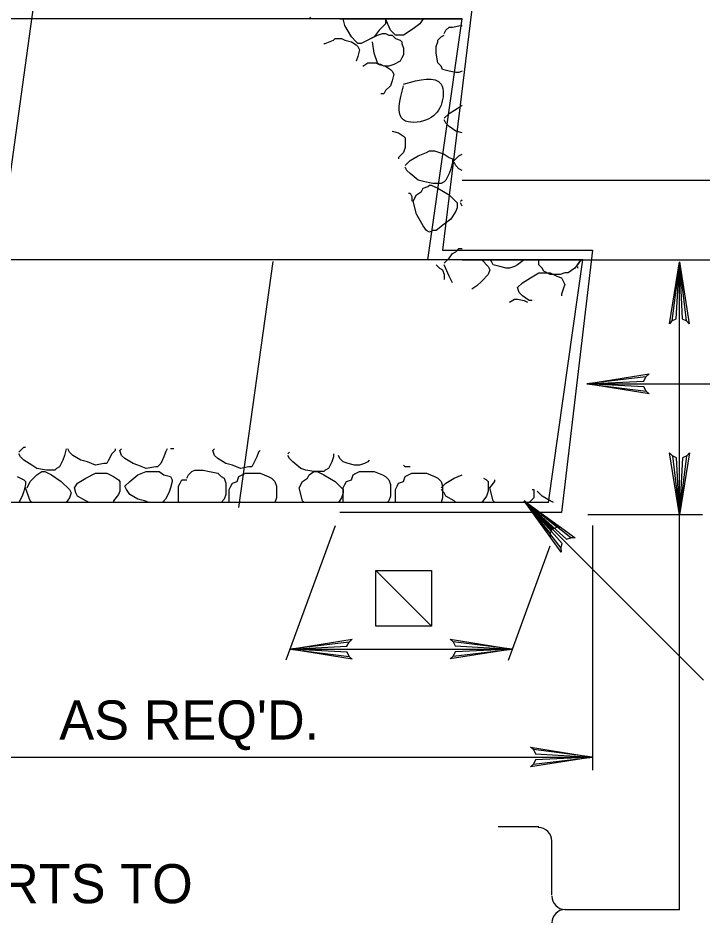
# Model space of a CAD drawing. Extents: x 593 to 1473, y 721 to 1315.
# Drawn here: x 928.2 to 980.7, y 1112.6 to 1182.1 of the extents above; entities that cross this region are included whole.
import ezdxf

# ---------------------------------------------------------------- set-up
doc = ezdxf.new("R2010")
doc.units = 0
doc.layers.add('1', color=7, linetype='Continuous')
doc.layers.add('2', color=7, linetype='Continuous')

msp = doc.modelspace()

# ---------------------------------------------------------------- linework, layer by layer
at = {"layer": '1'}
msp.add_line((959.933, 1135.405), (955.656, 1139.679), dxfattribs=at)
for points in [[(978.373, 1158.838), (978.701, 1159.007), (978.942, 1163.379), (978.373, 1158.838), (978.173, 1158.605), (978.942, 1163.379), (979.159, 1159.011), (979.484, 1158.851), (978.942, 1163.379), (979.701, 1158.605), (979.484, 1158.851)], [(978.373, 1158.838), (978.701, 1159.007), (978.942, 1163.379), (978.373, 1158.838), (978.173, 1158.605), (978.942, 1163.379), (979.159, 1159.011), (979.484, 1158.851), (978.942, 1163.379), (979.701, 1158.605), (979.484, 1158.851)], [(976.382, 1153.439), (976.213, 1153.768), (971.841, 1154.009), (976.382, 1153.439), (976.615, 1153.24), (971.841, 1154.009), (976.209, 1154.225), (976.369, 1154.55), (971.841, 1154.009), (976.615, 1154.768), (976.369, 1154.55)], [(979.513, 1148.491), (979.184, 1148.322), (978.942, 1143.95), (979.513, 1148.491), (979.712, 1148.724), (978.942, 1143.95), (978.726, 1148.318), (978.401, 1148.478), (978.942, 1143.95), (978.184, 1148.724), (978.401, 1148.478)], [(969.841, 1141.407), (969.954, 1141.759), (967.033, 1145.021), (969.841, 1141.407), (969.865, 1141.102), (967.033, 1145.021), (970.275, 1142.085), (970.617, 1142.202), (967.033, 1145.021), (970.945, 1142.182), (970.617, 1142.202)], [(953.617, 1133.08), (953.448, 1133.409), (949.076, 1133.65), (953.617, 1133.08), (953.85, 1132.881), (949.076, 1133.65), (953.444, 1133.866), (953.604, 1134.191), (949.076, 1133.65), (953.85, 1134.409), (953.604, 1134.191)], [(961.58, 1134.22), (961.749, 1133.891), (966.121, 1133.65), (961.58, 1134.22), (961.347, 1134.419), (966.121, 1133.65), (961.753, 1133.434), (961.593, 1133.109), (966.121, 1133.65), (961.347, 1132.891), (961.593, 1133.109)], [(961.58, 1134.22), (961.749, 1133.891), (966.121, 1133.65), (961.58, 1134.22), (961.347, 1134.419), (966.121, 1133.65), (961.753, 1133.434), (961.593, 1133.109), (966.121, 1133.65), (961.347, 1132.891), (961.593, 1133.109)], [(967.743, 1125.933), (967.912, 1125.605), (972.283, 1125.363), (967.743, 1125.933), (967.51, 1126.133), (972.283, 1125.363), (967.915, 1125.147), (967.756, 1124.822), (972.283, 1125.363), (967.51, 1124.605), (967.756, 1124.822)]]:
    msp.add_lwpolyline(points, dxfattribs=at)
for points in [[(959.933, 1135.405), (955.656, 1135.405), (955.656, 1139.679), (959.933, 1139.679)], [(959.933, 1135.405), (955.656, 1139.679), (959.933, 1139.679)]]:
    msp.add_lwpolyline(points, close=True, dxfattribs=at)
at = {"layer": '2'}
for p, q in [((924.158, 1145.021), (934.408, 1219.146)), ((963.033, 1182.771), (960.783, 1164.271)), ((962.283, 1182.021), (910.658, 1182.021)), ((952.908, 1182.021), (962.283, 1182.021)), ((959.658, 1163.521), (962.283, 1182.021)), ((962.283, 1169.646), (997.408, 1169.646)), ((960.783, 1164.271), (972.283, 1164.271)), ((972.283, 1164.271), (969.908, 1144.146)), ((971.533, 1163.521), (908.104, 1163.521)), ((945.158, 1144.521), (947.783, 1163.396)), ((962.283, 1163.521), (971.533, 1163.521)), ((968.908, 1144.896), (971.533, 1163.521)), ((971.533, 1163.521), (997.408, 1163.521)), ((978.942, 1143.95), (978.942, 1163.379)), ((971.841, 1154.009), (1024.591, 1154.009)), ((968.908, 1144.896), (905.658, 1144.896)), ((967.033, 1145.021), (980.783, 1131.271)), ((969.908, 1144.146), (952.908, 1144.146)), ((980.701, 1143.95), (971.924, 1143.95)), ((978.942, 1113.625), (978.942, 1143.95)), ((952.529, 1143.107), (948.765, 1132.798)), ((972.283, 1143.146), (972.283, 1124.363)), ((969.001, 1141.54), (965.803, 1132.78)), ((949.076, 1133.65), (966.121, 1133.65)), ((915.783, 1125.363), (972.283, 1125.363)), ((968.161, 1120), (965.036, 1120)), ((969.161, 1114.75), (969.161, 1118.875)), ((978.942, 1113.625), (970.161, 1113.625))]:
    msp.add_line(p, q, dxfattribs=at)
for points in [[(950.658, 1182.146), (950.533, 1182.021)], [(953.283, 1181.521), (953.158, 1182.021)], [(953.783, 1180.646), (953.283, 1181.521)], [(956.408, 1181.646), (955.908, 1181.146)], [(956.408, 1182.021), (956.408, 1182.021)], [(956.408, 1182.021), (956.408, 1181.646)], [(956.783, 1181.146), (956.408, 1182.021)], [(959.033, 1181.646), (958.533, 1181.271)], [(959.283, 1182.021), (959.033, 1181.646)], [(961.033, 1181.146), (961.283, 1181.396)], [(961.283, 1181.396), (961.533, 1181.396)], [(961.533, 1181.396), (962.158, 1181.521)], [(962.158, 1181.521), (962.283, 1181.521)], [(955.908, 1181.146), (955.533, 1180.646)], [(955.533, 1180.646), (955.783, 1180.771)], [(955.783, 1180.771), (956.158, 1180.896)], [(956.158, 1180.896), (956.408, 1180.896)], [(956.408, 1180.896), (956.658, 1180.771)], [(956.658, 1180.771), (956.908, 1180.771)], [(957.158, 1180.771), (956.783, 1181.146)], [(956.908, 1180.771), (957.158, 1180.521)], [(957.283, 1180.771), (957.158, 1180.771)], [(957.533, 1180.771), (957.283, 1180.771)], [(957.783, 1180.771), (957.533, 1180.771)], [(958.533, 1181.271), (957.783, 1180.771)], [(960.658, 1180.646), (960.908, 1180.771)], [(960.908, 1180.896), (961.033, 1181.146)], [(951.658, 1180.146), (951.783, 1180.146)], [(951.783, 1180.146), (952.408, 1180.396)], [(952.408, 1180.396), (952.533, 1180.521)], [(952.533, 1180.521), (953.033, 1180.521)], [(953.033, 1180.521), (953.283, 1180.396)], [(953.283, 1180.396), (953.783, 1180.271)], [(954.158, 1180.271), (953.783, 1180.646)], [(953.783, 1180.271), (954.158, 1180.021)], [(954.283, 1180.146), (954.158, 1180.271)], [(954.158, 1180.021), (954.283, 1179.896)], [(954.533, 1180.146), (954.283, 1180.146)], [(954.783, 1180.271), (954.533, 1180.146)], [(955.533, 1180.646), (954.783, 1180.271)], [(955.283, 1180.521), (955.533, 1180.646)], [(955.533, 1179.396), (955.408, 1180.271)], [(957.158, 1180.521), (957.533, 1180.396)], [(957.533, 1180.396), (957.658, 1180.271)], [(957.658, 1180.271), (957.658, 1180.146)], [(957.658, 1180.146), (957.783, 1179.771)], [(960.283, 1179.896), (960.408, 1180.271)], [(960.408, 1180.396), (960.658, 1180.646)], [(960.408, 1180.271), (960.408, 1180.396)], [(954.283, 1179.896), (954.408, 1179.646)], [(954.408, 1179.646), (954.283, 1179.146)], [(955.783, 1178.646), (955.533, 1179.396)], [(957.783, 1179.271), (957.658, 1179.021)], [(957.783, 1179.771), (957.783, 1179.521)], [(957.783, 1179.521), (957.783, 1179.271)], [(960.283, 1179.396), (960.283, 1179.896)], [(960.408, 1178.646), (960.283, 1179.396)], [(954.283, 1179.146), (954.158, 1178.771)], [(954.158, 1178.771), (954.158, 1178.771)], [(954.658, 1178.396), (955.033, 1178.646)], [(955.033, 1178.646), (955.158, 1178.646)], [(955.158, 1178.646), (955.658, 1178.646)], [(955.658, 1178.646), (955.908, 1178.521)], [(955.908, 1178.521), (955.783, 1178.646)], [(957.533, 1178.771), (957.033, 1178.521)], [(957.658, 1179.021), (957.533, 1178.771)], [(960.658, 1178.396), (960.408, 1178.646)], [(956.033, 1178.521), (955.908, 1178.521)], [(955.908, 1178.521), (956.408, 1178.396)], [(956.283, 1178.396), (956.033, 1178.521)], [(956.408, 1178.396), (956.283, 1178.396)], [(956.658, 1178.396), (956.408, 1178.396)], [(956.408, 1178.396), (956.783, 1178.146)], [(957.033, 1178.521), (956.658, 1178.396)], [(956.783, 1178.146), (956.908, 1178.021)], [(956.908, 1178.021), (957.033, 1177.771)], [(960.783, 1178.146), (960.658, 1178.396)], [(961.283, 1178.021), (960.783, 1178.146)], [(961.783, 1177.896), (961.283, 1178.021)], [(962.033, 1177.896), (961.783, 1177.896)], [(962.283, 1178.021), (962.033, 1177.896)], [(956.908, 1177.271), (956.783, 1176.896)], [(957.033, 1177.771), (956.908, 1177.271)], [(956.408, 1176.521), (956.283, 1176.271)], [(956.783, 1176.896), (956.408, 1176.521)], [(956.158, 1176.271), (956.033, 1176.271)], [(956.283, 1176.271), (956.158, 1176.271)], [(961.283, 1174.771), (961.908, 1175.146)], [(961.908, 1175.146), (962.283, 1175.396)], [(960.908, 1174.396), (961.283, 1174.771)], [(961.033, 1174.021), (960.908, 1174.271)], [(961.283, 1173.771), (961.033, 1174.021)], [(961.783, 1173.396), (961.283, 1173.771)], [(956.908, 1173.396), (956.908, 1173.396)], [(956.908, 1173.396), (957.408, 1173.271)], [(957.408, 1173.271), (957.783, 1173.021)], [(957.783, 1173.021), (957.908, 1172.896)], [(962.283, 1173.271), (961.783, 1173.396)], [(957.908, 1172.896), (957.908, 1172.646)], [(957.908, 1172.646), (957.908, 1172.146)], [(957.783, 1171.771), (957.408, 1171.396)], [(957.908, 1172.146), (957.783, 1171.771)], [(958.908, 1171.521), (959.533, 1171.771)], [(959.533, 1171.771), (959.783, 1171.896)], [(959.783, 1171.896), (960.158, 1171.896)], [(960.158, 1171.896), (960.533, 1171.771)], [(960.533, 1171.771), (960.908, 1171.646)], [(960.908, 1171.646), (961.283, 1171.396)], [(962.033, 1171.521), (962.283, 1171.646)], [(957.408, 1171.396), (957.408, 1171.271)], [(957.908, 1170.771), (958.283, 1171.146)], [(958.283, 1171.146), (958.908, 1171.521)], [(961.283, 1171.396), (961.533, 1171.271)], [(961.533, 1171.021), (961.408, 1170.521)], [(961.533, 1171.271), (961.533, 1171.021)], [(961.658, 1171.146), (962.033, 1171.521)], [(961.783, 1170.771), (961.658, 1171.021)], [(958.033, 1170.396), (957.908, 1170.646)], [(958.283, 1170.146), (958.033, 1170.396)], [(961.408, 1170.521), (961.283, 1170.146)], [(962.033, 1170.521), (961.783, 1170.771)], [(962.283, 1170.396), (962.033, 1170.521)], [(958.908, 1169.646), (958.283, 1170.146)], [(959.408, 1169.521), (958.908, 1169.646)], [(961.033, 1169.646), (960.908, 1169.521)], [(961.283, 1170.146), (961.033, 1169.646)], [(959.158, 1168.771), (959.283, 1169.021)], [(959.283, 1169.021), (959.658, 1169.146)], [(960.033, 1169.396), (959.408, 1169.521)], [(959.658, 1169.146), (959.783, 1169.271)], [(959.783, 1169.271), (959.908, 1169.271)], [(959.908, 1169.271), (960.408, 1169.021)], [(960.658, 1169.396), (960.033, 1169.396)], [(960.408, 1169.021), (961.283, 1168.521)], [(960.908, 1169.521), (960.658, 1169.396)], [(958.158, 1168.646), (958.283, 1168.646)], [(958.283, 1168.646), (958.408, 1168.396)], [(958.408, 1168.396), (958.408, 1168.271)], [(958.408, 1168.271), (958.408, 1168.021)], [(958.533, 1168.021), (958.783, 1168.521)], [(958.783, 1168.521), (959.158, 1168.771)], [(961.283, 1168.521), (961.908, 1167.896)], [(958.783, 1167.021), (958.533, 1168.021)], [(961.908, 1167.521), (961.783, 1167.271)], [(961.908, 1167.896), (961.908, 1167.521)], [(962.158, 1168.021), (962.283, 1168.146)], [(962.283, 1167.646), (962.158, 1167.896)], [(959.283, 1166.146), (958.783, 1167.021)], [(961.783, 1167.271), (961.408, 1166.646)], [(959.533, 1165.771), (959.283, 1166.146)], [(960.908, 1166.271), (960.283, 1165.771)], [(961.408, 1166.646), (960.908, 1166.271)], [(959.783, 1165.646), (959.533, 1165.771)], [(960.033, 1165.771), (959.783, 1165.646)], [(960.283, 1165.771), (960.033, 1165.771)], [(961.283, 1163.646), (961.533, 1164.021)], [(961.533, 1164.021), (961.783, 1164.146)], [(961.783, 1164.146), (962.033, 1164.396)], [(962.033, 1164.396), (962.158, 1164.396)], [(962.158, 1164.396), (962.283, 1164.396)], [(960.908, 1163.271), (961.283, 1163.646)], [(963.783, 1163.521), (964.283, 1163.021)], [(964.533, 1163.396), (964.408, 1163.521)], [(964.658, 1163.146), (964.533, 1163.396)], [(967.033, 1163.521), (966.533, 1163.146)], [(968.158, 1163.146), (968.158, 1163.521)], [(971.283, 1163.396), (970.908, 1162.896)], [(971.158, 1163.146), (971.408, 1163.521)], [(971.408, 1163.521), (971.283, 1163.396)], [(960.283, 1163.146), (960.283, 1163.146)], [(960.283, 1163.146), (960.533, 1162.896)], [(960.533, 1162.896), (960.783, 1162.771)], [(960.783, 1162.771), (960.908, 1162.396)], [(961.283, 1162.271), (960.908, 1163.146)], [(964.283, 1163.021), (964.408, 1162.771)], [(964.408, 1162.771), (964.283, 1162.396)], [(965.158, 1163.021), (964.658, 1163.146)], [(965.658, 1162.896), (965.158, 1163.021)], [(965.908, 1162.896), (965.658, 1162.896)], [(966.283, 1163.021), (965.908, 1162.896)], [(966.533, 1163.146), (966.283, 1163.021)], [(968.408, 1162.896), (968.158, 1163.146)], [(968.533, 1162.646), (968.408, 1162.896)], [(969.033, 1162.396), (968.533, 1162.646)], [(970.908, 1162.896), (970.408, 1162.521)], [(971.158, 1162.896), (971.158, 1163.021)], [(960.908, 1162.396), (960.908, 1162.021)], [(960.908, 1162.021), (960.908, 1162.021)], [(961.533, 1161.771), (961.283, 1162.271)], [(964.283, 1162.396), (963.783, 1161.896)], [(966.908, 1161.771), (967.533, 1162.146)], [(967.533, 1162.146), (968.158, 1162.521)], [(968.158, 1162.521), (968.283, 1162.521)], [(968.283, 1162.521), (968.783, 1162.521)], [(968.783, 1162.521), (969.033, 1162.521)], [(969.033, 1162.521), (969.533, 1162.271)], [(969.408, 1162.396), (969.033, 1162.396)], [(969.783, 1162.396), (969.408, 1162.396)], [(969.533, 1162.271), (969.908, 1162.146)], [(970.158, 1162.521), (969.783, 1162.396)], [(969.908, 1162.146), (970.033, 1161.896)], [(970.408, 1162.521), (970.158, 1162.521)], [(963.408, 1161.521), (963.033, 1161.271)], [(963.783, 1161.896), (963.408, 1161.521)], [(966.533, 1161.396), (966.908, 1161.771)], [(966.658, 1161.021), (966.533, 1161.396)], [(970.033, 1161.271), (969.908, 1160.896)], [(970.033, 1161.896), (970.158, 1161.646)], [(970.158, 1161.646), (970.033, 1161.271)], [(965.908, 1160.271), (966.283, 1160.521)], [(966.283, 1160.521), (966.408, 1160.521)], [(966.408, 1160.521), (966.533, 1160.521)], [(966.533, 1160.521), (967.033, 1160.396)], [(966.908, 1160.771), (966.658, 1161.021)], [(967.408, 1160.396), (966.908, 1160.771)], [(969.908, 1160.896), (969.908, 1160.771)], [(965.908, 1160.271), (965.908, 1160.271)], [(967.033, 1160.396), (967.283, 1160.271)], [(967.658, 1160.396), (967.408, 1160.396)], [(928.283, 1148.771), (928.658, 1149.146)], [(928.658, 1149.146), (928.783, 1149.146)], [(931.908, 1149.021), (931.783, 1148.521)], [(931.908, 1149.021), (931.908, 1149.021)], [(932.158, 1148.771), (932.033, 1149.021)], [(932.408, 1148.521), (932.158, 1148.771)], [(935.658, 1148.896), (935.408, 1148.646)], [(935.658, 1149.021), (935.658, 1148.896)], [(936.033, 1148.896), (936.158, 1149.021)], [(936.158, 1148.521), (936.033, 1148.896)], [(939.533, 1148.771), (939.408, 1148.396)], [(939.658, 1149.021), (939.533, 1148.771)], [(940.158, 1149.021), (939.908, 1149.021)], [(939.908, 1149.021), (939.908, 1149.021)], [(940.158, 1149.021), (940.158, 1149.021)], [(943.158, 1148.896), (943.283, 1149.021)], [(943.283, 1148.521), (943.158, 1148.896)], [(946.658, 1148.771), (946.533, 1148.396)], [(946.783, 1148.896), (946.658, 1148.771)], [(948.908, 1148.646), (949.033, 1148.771)], [(928.408, 1148.396), (928.283, 1148.646)], [(928.658, 1148.146), (928.408, 1148.396)], [(929.283, 1147.771), (928.658, 1148.146)], [(931.658, 1148.146), (931.408, 1147.646)], [(931.783, 1148.521), (931.658, 1148.146)], [(933.033, 1148.146), (932.408, 1148.521)], [(933.533, 1148.021), (933.033, 1148.146)], [(934.158, 1147.771), (933.533, 1148.021)], [(935.158, 1148.146), (935.033, 1147.896)], [(935.408, 1148.646), (935.158, 1148.146)], [(936.408, 1148.271), (936.158, 1148.521)], [(937.033, 1147.896), (936.408, 1148.271)], [(939.408, 1148.396), (939.158, 1147.896)], [(943.533, 1148.271), (943.283, 1148.521)], [(944.158, 1147.896), (943.533, 1148.271)], [(946.533, 1148.396), (946.283, 1147.896)], [(949.033, 1148.271), (948.908, 1148.521)], [(949.283, 1148.021), (949.033, 1148.271)], [(949.908, 1147.521), (949.283, 1148.021)], [(952.283, 1148.021), (952.033, 1147.521)], [(952.408, 1148.396), (952.283, 1148.021)], [(952.408, 1148.646), (952.408, 1148.396)], [(952.908, 1148.271), (952.783, 1148.521)], [(953.158, 1148.021), (952.908, 1148.271)], [(953.533, 1147.896), (953.158, 1148.021)], [(955.033, 1148.021), (954.783, 1147.896)], [(955.158, 1148.146), (955.033, 1148.021)], [(929.658, 1147.521), (929.283, 1147.771)], [(930.408, 1147.396), (929.658, 1147.521)], [(931.033, 1147.396), (930.408, 1147.396)], [(931.158, 1147.521), (931.033, 1147.396)], [(931.408, 1147.646), (931.158, 1147.521)], [(934.783, 1147.896), (934.158, 1147.771)], [(935.033, 1147.896), (934.783, 1147.896)], [(937.408, 1147.771), (937.033, 1147.896)], [(938.033, 1147.521), (937.408, 1147.771)], [(938.783, 1147.646), (938.033, 1147.521)], [(938.908, 1147.646), (938.783, 1147.646)], [(939.158, 1147.896), (938.908, 1147.646)], [(941.533, 1147.271), (941.783, 1147.396)], [(941.783, 1147.396), (942.408, 1147.396)], [(942.408, 1147.396), (942.908, 1147.271)], [(944.658, 1147.771), (944.158, 1147.896)], [(945.283, 1147.521), (944.658, 1147.771)], [(945.908, 1147.646), (945.283, 1147.521)], [(946.158, 1147.646), (945.908, 1147.646)], [(946.283, 1147.896), (946.158, 1147.646)], [(950.283, 1147.396), (949.908, 1147.521)], [(950.908, 1147.271), (950.283, 1147.396)], [(951.783, 1147.396), (951.658, 1147.271)], [(952.033, 1147.521), (951.783, 1147.396)], [(954.033, 1147.771), (953.533, 1147.896)], [(954.408, 1147.771), (954.033, 1147.771)], [(954.783, 1147.896), (954.408, 1147.771)], [(957.908, 1147.646), (957.783, 1147.771)], [(957.783, 1147.771), (957.783, 1147.771)], [(958.158, 1147.646), (957.908, 1147.646)], [(958.283, 1147.646), (958.158, 1147.646)], [(928.158, 1146.896), (928.658, 1146.646)], [(928.658, 1146.646), (928.783, 1146.521)], [(929.158, 1146.521), (929.408, 1146.771)], [(929.408, 1146.771), (929.658, 1147.021)], [(929.658, 1147.021), (930.033, 1147.271)], [(930.033, 1147.271), (930.158, 1147.271)], [(930.158, 1147.271), (930.283, 1147.271)], [(930.283, 1147.271), (930.783, 1147.021)], [(930.783, 1147.021), (931.533, 1146.521)], [(932.783, 1146.396), (933.408, 1146.771)], [(933.408, 1146.771), (934.158, 1147.146)], [(934.158, 1147.146), (934.283, 1147.146)], [(934.283, 1147.146), (934.783, 1147.146)], [(934.783, 1147.146), (935.033, 1147.146)], [(935.033, 1147.146), (935.533, 1146.896)], [(935.533, 1146.896), (935.908, 1146.646)], [(935.908, 1146.646), (936.033, 1146.521)], [(936.783, 1146.521), (937.408, 1147.021)], [(937.408, 1147.021), (938.033, 1147.271)], [(938.033, 1147.271), (938.283, 1147.271)], [(938.283, 1147.271), (938.658, 1147.271)], [(938.658, 1147.271), (939.033, 1147.271)], [(939.033, 1147.271), (939.408, 1147.021)], [(939.408, 1147.021), (939.908, 1146.896)], [(939.908, 1146.896), (940.033, 1146.646)], [(940.033, 1146.646), (940.033, 1146.521)], [(940.658, 1146.396), (940.783, 1146.646)], [(940.783, 1146.646), (941.158, 1146.646)], [(941.158, 1146.771), (941.283, 1147.021)], [(941.283, 1147.021), (941.533, 1147.271)], [(942.908, 1147.271), (943.533, 1147.146)], [(943.533, 1147.146), (943.783, 1146.896)], [(943.783, 1146.896), (944.033, 1146.771)], [(944.033, 1146.771), (944.158, 1146.396)], [(945.033, 1146.521), (945.158, 1146.896)], [(945.158, 1146.896), (945.408, 1147.021)], [(945.408, 1147.021), (945.658, 1147.146)], [(945.658, 1147.146), (946.283, 1147.146)], [(946.283, 1147.146), (946.783, 1147.146)], [(946.783, 1147.146), (947.408, 1146.896)], [(947.408, 1146.896), (947.658, 1146.771)], [(947.658, 1146.771), (947.908, 1146.521)], [(950.033, 1146.521), (950.408, 1146.771)], [(950.408, 1146.771), (950.533, 1147.021)], [(950.533, 1147.021), (950.908, 1147.271)], [(950.908, 1147.271), (951.033, 1147.271)], [(951.658, 1147.271), (950.908, 1147.271)], [(951.033, 1147.271), (951.158, 1147.271)], [(951.158, 1147.271), (951.658, 1147.021)], [(951.658, 1147.021), (952.533, 1146.521)], [(953.408, 1146.521), (953.783, 1146.646)], [(953.783, 1146.646), (953.908, 1147.021)], [(953.908, 1147.021), (954.158, 1147.146)], [(954.158, 1147.146), (954.408, 1147.271)], [(954.408, 1147.271), (955.033, 1147.271)], [(955.033, 1147.271), (955.533, 1147.271)], [(955.533, 1147.271), (956.158, 1147.021)], [(956.158, 1147.021), (956.408, 1146.896)], [(956.408, 1146.896), (956.658, 1146.646)], [(956.658, 1146.646), (956.783, 1146.271)], [(957.783, 1146.521), (957.908, 1146.896)], [(957.908, 1146.896), (958.158, 1147.021)], [(958.158, 1147.021), (958.408, 1147.146)], [(958.408, 1147.146), (959.033, 1147.146)], [(959.033, 1147.146), (959.533, 1147.146)], [(959.533, 1147.146), (960.158, 1146.896)], [(960.158, 1146.896), (960.408, 1146.771)], [(960.408, 1146.771), (960.658, 1146.521)], [(961.033, 1146.396), (961.658, 1146.771)], [(961.658, 1146.771), (962.283, 1147.021)], [(963.908, 1146.771), (964.158, 1146.646)], [(964.158, 1146.646), (964.283, 1146.521)], [(964.783, 1146.521), (964.783, 1146.646)], [(928.783, 1146.271), (928.658, 1145.771)], [(928.783, 1146.521), (928.783, 1146.271)], [(929.158, 1145.021), (928.783, 1146.021)], [(928.908, 1146.021), (929.158, 1146.521)], [(931.533, 1146.521), (932.158, 1145.896)], [(932.533, 1146.021), (932.783, 1146.396)], [(932.658, 1145.646), (932.533, 1146.021)], [(936.033, 1146.521), (936.033, 1146.271)], [(936.033, 1146.271), (936.033, 1145.771)], [(936.408, 1146.146), (936.783, 1146.521)], [(936.533, 1145.896), (936.408, 1146.146)], [(939.908, 1146.021), (939.783, 1145.646)], [(940.033, 1146.521), (939.908, 1146.021)], [(940.533, 1146.146), (940.658, 1146.396)], [(940.533, 1145.771), (940.533, 1146.146)], [(944.158, 1146.396), (944.158, 1146.021)], [(944.158, 1146.021), (944.158, 1145.771)], [(944.408, 1145.896), (944.533, 1146.146)], [(944.533, 1146.146), (944.658, 1146.396)], [(944.658, 1146.396), (945.033, 1146.521)], [(947.908, 1146.521), (948.033, 1146.146)], [(948.033, 1146.146), (948.033, 1145.896)], [(949.783, 1146.021), (950.033, 1146.521)], [(950.033, 1145.021), (949.783, 1146.021)], [(952.533, 1146.521), (953.158, 1145.896)], [(953.158, 1146.021), (953.283, 1146.271)], [(953.158, 1145.646), (953.158, 1146.021)], [(953.283, 1146.271), (953.408, 1146.521)], [(956.783, 1146.271), (956.783, 1146.021)], [(956.783, 1146.021), (956.783, 1145.771)], [(957.158, 1145.896), (957.283, 1146.146)], [(957.283, 1146.146), (957.408, 1146.396)], [(957.408, 1146.396), (957.783, 1146.521)], [(960.658, 1146.521), (960.783, 1146.146)], [(960.658, 1146.021), (961.033, 1146.396)], [(960.783, 1146.146), (960.783, 1145.896)], [(964.283, 1146.521), (964.283, 1146.271)], [(964.283, 1146.271), (964.283, 1145.771)], [(964.408, 1146.021), (964.783, 1146.521)], [(964.658, 1145.021), (964.408, 1146.021)], [(928.533, 1145.396), (928.283, 1144.896)], [(928.658, 1145.771), (928.533, 1145.396)], [(932.158, 1145.271), (931.908, 1144.896)], [(932.158, 1145.896), (932.283, 1145.646)], [(932.283, 1145.646), (932.158, 1145.271)], [(932.783, 1145.396), (932.658, 1145.646)], [(933.408, 1145.021), (932.783, 1145.396)], [(935.908, 1145.521), (935.533, 1145.021)], [(936.033, 1145.771), (935.908, 1145.521)], [(936.783, 1145.521), (936.533, 1145.896)], [(937.408, 1145.146), (936.783, 1145.521)], [(939.783, 1145.646), (939.533, 1145.146)], [(940.533, 1145.271), (940.533, 1145.771)], [(940.533, 1144.896), (940.533, 1145.271)], [(944.158, 1145.521), (944.033, 1145.146)], [(944.158, 1145.771), (944.158, 1145.521)], [(944.408, 1145.521), (944.408, 1145.896)], [(944.408, 1145.021), (944.408, 1145.521)], [(948.033, 1145.271), (947.908, 1144.896)], [(948.033, 1145.896), (948.033, 1145.646)], [(948.033, 1145.646), (948.033, 1145.271)], [(953.033, 1145.271), (952.783, 1144.896)], [(953.158, 1145.646), (953.033, 1145.271)], [(953.158, 1145.896), (953.158, 1145.646)], [(953.158, 1145.146), (953.158, 1145.646)], [(956.783, 1145.396), (956.658, 1145.021)], [(956.783, 1145.771), (956.783, 1145.396)], [(957.158, 1145.521), (957.158, 1145.896)], [(957.158, 1145.021), (957.158, 1145.521)], [(960.908, 1145.646), (960.658, 1145.896)], [(960.783, 1145.271), (960.658, 1144.896)], [(960.783, 1145.896), (960.783, 1145.646)], [(960.783, 1145.646), (960.783, 1145.271)], [(961.033, 1145.396), (960.908, 1145.646)], [(961.658, 1145.021), (961.033, 1145.396)], [(964.158, 1145.396), (963.783, 1144.896)], [(964.283, 1145.771), (964.158, 1145.396)], [(967.783, 1145.271), (967.408, 1144.896)], [(967.658, 1145.896), (967.783, 1145.896)], [(967.783, 1145.896), (967.783, 1145.646)], [(967.783, 1145.646), (967.783, 1145.271)], [(968.158, 1145.646), (968.033, 1145.771)], [(968.408, 1145.396), (968.158, 1145.646)], [(969.033, 1145.021), (968.408, 1145.396)], [(928.283, 1144.896), (928.283, 1144.896)], [(929.283, 1144.896), (929.158, 1145.021)], [(933.658, 1144.896), (933.408, 1145.021)], [(935.533, 1145.021), (935.533, 1144.896)], [(937.908, 1145.021), (937.408, 1145.146)], [(938.283, 1144.896), (937.908, 1145.021)], [(939.408, 1145.021), (939.283, 1144.896)], [(939.533, 1145.146), (939.408, 1145.021)], [(944.033, 1145.146), (943.783, 1144.896)], [(944.408, 1144.896), (944.408, 1145.021)], [(947.908, 1144.896), (947.908, 1144.896)], [(950.158, 1144.896), (950.033, 1145.021)], [(953.158, 1144.896), (953.158, 1145.146)], [(956.658, 1145.021), (956.533, 1144.896)], [(957.158, 1144.896), (957.158, 1145.021)], [(960.658, 1144.896), (960.658, 1144.896)], [(961.783, 1144.896), (961.658, 1145.021)], [(963.783, 1144.896), (963.783, 1144.896)], [(964.783, 1144.896), (964.658, 1145.021)], [(969.033, 1142.521), (969.158, 1142.771), (967.033, 1145.021), (969.033, 1142.521), (969.033, 1142.271), (967.033, 1145.021), (969.283, 1142.896), (969.533, 1143.021), (967.033, 1145.021), (969.783, 1143.021), (969.533, 1143.021)], [(969.283, 1144.896), (969.033, 1145.021)]]:
    msp.add_lwpolyline(points, dxfattribs=at)
for centre, start, end in [((968.121, 1118.919), 0, 90), ((970.184, 1114.696), 180, 270), ((970.184, 1112.633), 90, 180)]:
    msp.add_arc(centre, 1.031, start, end, dxfattribs=at)
msp.add_spline([(957.783, 1177.021), (960.658, 1177.021), (960.658, 1175.396), (959.533, 1174.271), (957.783, 1174.271), (957.783, 1176.896)], degree=3, dxfattribs=at)

# ---------------------------------------------------------------- texts
for s, p in [("AS REQ'D.", (931.379, 1126.709)), ('3\'-0" MIN. FOR BOX CULVERTS TO', (875.674, 1114.144))]:
    msp.add_text(s, height=3, dxfattribs=at).set_placement(p)

doc.saveas('drawing.dxf')
